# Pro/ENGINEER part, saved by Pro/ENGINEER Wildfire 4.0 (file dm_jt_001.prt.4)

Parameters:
  METRIC = "NO"

Other parameters: PITCH, DRILL_DIAMETER, THREAD_DIAMETER, THREADS_PER_INCH, THREAD_DEPTH, THREAD_LENGTH, DRILL_POINT_ANGLE, DRILL_DEPTH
